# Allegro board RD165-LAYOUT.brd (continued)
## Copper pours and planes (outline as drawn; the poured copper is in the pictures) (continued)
L_GND on BOTTOM: 69,16.69 68.99,16.65 68.97,16.62 68.38,16.03 68.35,16.01 68.31,16 58.17,16 58.01,16.03 57.88,16.12 57.62,16.38 57.53,16.51 57.5,16.67 57.5,52.13 57.53,52.29 57.62,52.42 57.88,52.68 58.01,52.77 58.17,52.8 67.21,52.8 67.25,52.79 67.28,52.77 71.72,48.33 71.74,48.3 71.75,48.26 71.75,36.54 71.74,36.5 71.72,36.47 69.09,33.84 69.02,33.74 69,33.63 ; 8 cut-outs
L_GND on CONDUCTIVE2: 69,16.69 68.99,16.65 68.97,16.62 68.38,16.03 68.35,16.01 68.31,16 58.17,16 58.01,16.03 57.88,16.12 57.62,16.38 57.53,16.51 57.5,16.67 57.5,52.13 57.53,52.29 57.62,52.42 57.88,52.68 58.01,52.77 58.17,52.8 67.21,52.8 67.25,52.79 67.28,52.77 71.72,48.33 71.74,48.3 71.75,48.26 71.75,36.54 71.74,36.5 71.72,36.47 69.09,33.84 69.02,33.74 69,33.63 ; 11 cut-outs
L_GND on CONDUCTIVE3: outline of 86 points within 57.5,16 71.75,52.8 ; 8 cut-outs
Net_1 on BOTTOM: 106.21,-1 106.65,-2.06 107.71,-2.5 109,-2.5 109,-6 1,-6 1,-2.5 2.29,-2.5 3.35,-2.06 3.79,-1 ; 4 cut-outs
Net_2 on BOTTOM: 1,112.5 1,116 109,116 109,112.5 107.71,112.5 106.65,112.06 106.21,111 3.79,111 3.35,112.06 2.29,112.5 ; 4 cut-outs
Net_3 on CONDUCTIVE3: 106.21,-1 106.65,-2.06 107.71,-2.5 109,-2.5 109,-6 1,-6 1,-2.5 2.29,-2.5 3.35,-2.06 3.79,-1 ; 2 cut-outs
Net_4 on CONDUCTIVE3: 1,112.5 1,116 109,116 109,112.5 107.71,112.5 106.65,112.06 106.21,111 3.79,111 3.35,112.06 2.29,112.5 ; 2 cut-outs
Net_5 on CONDUCTIVE2: 106.21,-1 106.65,-2.06 107.71,-2.5 109,-2.5 109,-6 1,-6 1,-2.5 2.29,-2.5 3.35,-2.06 3.79,-1 ; 2 cut-outs
Net_6 on CONDUCTIVE2: 1,112.5 1,116 109,116 109,112.5 107.71,112.5 106.65,112.06 106.21,111 3.79,111 3.35,112.06 2.29,112.5 ; 2 cut-outs
Net_7 on TOP: 106.21,-1 106.65,-2.06 107.71,-2.5 109,-2.5 109,-6 1,-6 1,-2.5 2.29,-2.5 3.35,-2.06 3.79,-1 ; 4 cut-outs
Net_8 on TOP: 1,112.5 1,116 109,116 109,112.5 107.71,112.5 106.65,112.06 106.21,111 3.79,111 3.35,112.06 2.29,112.5 ; 4 cut-outs
O_GND on TOP (solid shape): 85.12,80.86 85.2,80.79 85.22,80.69 85.22,77.5 83.78,77.5 83.78,80.89 85.03,80.89
O_GND on TOP: outline of 102 points within 56.8,1 109,109 ; 7 cut-outs
O_GND on BOTTOM: 57.5,15.08 57.53,15.24 57.62,15.37 57.88,15.63 58.01,15.72 58.17,15.75 68.31,15.75 68.44,15.78 68.56,15.85 69.15,16.44 69.22,16.56 69.25,16.69 69.25,33.6 69.26,33.64 69.28,33.68 71.65,36.04 71.9,36.29 71.97,36.41 72,36.54 72,48.26 71.97,48.39 71.9,48.51 67.46,52.95 67.34,53.02 67.21,53.05 58.17,53.05 58.01,53.08 57.88,53.17 57.62,53.43 57.53,53.56 57.5,53.72 57.5,108.33 57.53,108.49 57.62,108.62 57.88,108.88 58.01,108.97 58.17,109 99.86,109 99.9,108.99 99.93,108.97 100.17,108.73 100.19,108.7 100.2,108.66 100.2,106 101.9,101.9 106,100.2 108.66,100.2 108.7,100.19 108.73,100.17 108.97,99.93 108.99,99.9 109,99.86 109,10.14 108.99,10.1 108.97,10.07 108.73,9.83 108.7,9.81 108.66,9.8 106,9.8 101.9,8.1 100.2,4 100.2,1.34 100.19,1.3 100.17,1.27 99.93,1.03 99.9,1.01 99.86,1 58.17,1 58.01,1.03 57.88,1.12 57.62,1.38 57.53,1.51 57.5,1.67 ; 9 cut-outs
O_GND on CONDUCTIVE2: 57.5,15.08 57.53,15.24 57.62,15.37 57.88,15.63 58.01,15.72 58.17,15.75 68.31,15.75 68.44,15.78 68.56,15.85 69.15,16.44 69.22,16.56 69.25,16.69 69.25,33.6 69.26,33.64 69.28,33.68 71.9,36.29 71.97,36.41 72,36.54 72,48.26 71.97,48.39 71.9,48.51 67.46,52.95 67.34,53.02 67.21,53.05 58.17,53.05 58.01,53.08 57.88,53.17 57.62,53.43 57.53,53.56 57.5,53.72 57.5,108.33 57.53,108.49 57.62,108.62 57.88,108.88 58.01,108.97 58.17,109 99.86,109 99.9,108.99 99.93,108.97 100.17,108.73 100.19,108.7 100.2,108.66 100.2,106 101.9,101.9 106,100.2 108.66,100.2 108.7,100.19 108.73,100.17 108.97,99.93 108.99,99.9 109,99.86 109,10.14 108.99,10.1 108.97,10.07 108.73,9.83 108.7,9.81 108.66,9.8 106,9.8 101.9,8.1 100.2,4 100.2,1.34 100.19,1.3 100.17,1.27 99.93,1.03 99.9,1.01 99.86,1 58.17,1 58.01,1.03 57.88,1.12 57.62,1.38 57.53,1.51 57.5,1.67 ; 13 cut-outs
O_GND on CONDUCTIVE3: outline of 186 points within 57.5,1 109,109 ; 10 cut-outs
P-GND on TOP: outline of 168 points within 29.95,2.25 46.9,19
P-GND on TOP: 23.39,78.4 23.35,78.41 23.32,78.43 23.08,78.67 23.06,78.7 23.05,78.74 23.05,78.79 23.01,79.02 22.88,79.25 22.88,79.28 22.88,79.53 22.88,79.57 22.9,79.6 23.07,79.77 23.1,79.79 23.14,79.8 23.95,79.8 24.23,79.87 24.34,79.96 25.1,80.72 25.13,80.74 25.17,80.75 25.46,80.75 25.54,80.72 25.57,80.65 25.57,79.8 25.54,79.73 25.46,79.7 25.18,79.7 24.98,79.62 24.9,79.42 24.9,78.69 24.89,78.65 24.87,78.62 24.68,78.43 24.65,78.41 24.61,78.4
P-GND on TOP: 52.5,60.81 52.54,60.62 52.65,60.45 53.05,60.05 53.16,59.88 53.2,59.69 53.2,56.31 53.16,56.12 53.05,55.95 52.65,55.55 52.54,55.38 52.5,55.19 52.5,1.67 52.47,1.51 51.99,1.03 51.83,1 10.14,1 10.1,1.01 10.07,1.03 9.83,1.27 9.81,1.3 9.8,1.34 9.8,4 8.1,8.1 4,9.8 1.34,9.8 1.3,9.81 1.27,9.83 1.03,10.07 1.01,10.1 1,10.14 1,99.86 1.01,99.9 1.03,99.93 1.27,100.17 1.3,100.19 1.34,100.2 4,100.2 8.1,101.9 9.8,106 9.8,108.66 9.81,108.7 9.83,108.73 10.07,108.97 10.1,108.99 10.14,109 51.83,109 51.99,108.97 52.12,108.88 52.38,108.62 52.47,108.49 52.5,108.33 ; 28 cut-outs
P-GND on BOTTOM: 52.5,1.67 52.47,1.51 52.38,1.38 51.99,1.03 51.83,1 10.14,1 10.1,1.01 10.07,1.03 9.83,1.27 9.81,1.3 9.8,1.34 9.8,4 8.1,8.1 4,9.8 1.34,9.8 1.3,9.81 1.27,9.83 1.03,10.07 1.01,10.1 1,10.14 1,99.86 1.01,99.9 1.03,99.93 1.27,100.17 1.3,100.19 1.34,100.2 4,100.2 8.1,101.9 9.8,106 9.8,108.66 9.81,108.7 9.83,108.73 10.07,108.97 10.1,108.99 10.14,109 51.83,109 51.99,108.97 52.12,108.88 52.38,108.62 52.38,108.62 52.47,108.49 52.5,108.33 ; 22 cut-outs
P-GND on CONDUCTIVE2: 52.5,1.67 52.47,1.51 52.38,1.38 52.12,1.12 51.99,1.03 51.83,1 10.14,1 10.1,1.01 10.07,1.03 9.83,1.27 9.81,1.3 9.8,1.34 9.8,4 8.1,8.1 4,9.8 1.34,9.8 1.3,9.81 1.27,9.83 1.03,10.07 1.01,10.1 1,10.14 1,99.86 1.01,99.9 1.03,99.93 1.27,100.17 1.3,100.19 1.34,100.2 4,100.2 8.1,101.9 9.8,106 9.8,108.66 9.81,108.7 9.83,108.73 10.07,108.97 10.1,108.99 10.14,109 51.83,109 51.99,108.97 52.12,108.88 52.38,108.62 52.47,108.49 52.5,108.33 ; 40 cut-outs
VOUT on TOP: 103.9,83.5 103.83,83.53 103.8,83.6 103.8,83.99 103.77,84.09 103.74,84.13 102.6,85.28 101.67,85.28 101.6,85.3 101.58,85.38 101.58,85.88 101.6,85.95 101.67,85.97 102.98,85.97 103.02,85.97 103.05,85.95 104.48,84.52 104.57,84.39 104.6,84.23 104.6,83.6 104.57,83.53 104.5,83.5
VOUT on TOP: 80.24,21 80.2,21.01 80.17,21.03 78.18,23.02 78.16,23.05 78.15,23.09 78.15,32.51 78.16,32.55 78.18,32.58 79.27,33.67 79.3,33.69 79.34,33.7 81.91,33.7 81.95,33.69 81.98,33.67 82.52,33.13 82.66,33.03 82.84,33 88.87,33 88.94,33.02 89.01,33.06 89.44,33.49 89.48,33.56 89.5,33.63 89.5,37.96 89.51,38 89.53,38.03 89.77,38.27 89.8,38.29 89.84,38.3 90.6,38.3 90.68,38.32 90.74,38.36 91.04,38.66 91.08,38.72 91.1,38.8 91.1,41.5 91.13,41.57 91.2,41.6 95.8,41.6 95.87,41.57 95.9,41.5 95.9,38.8 95.93,38.7 95.96,38.65 96.05,38.6 96.1,38.59 101.37,38.59 101.4,38.58 101.44,38.56 101.47,38.53 101.49,38.5 101.5,38.46 101.5,23.64 101.49,23.6 101.47,23.57 98.93,21.03 98.9,21.01 98.86,21
VOUT on BOTTOM: 80.24,21 80.2,21.01 80.17,21.03 78.18,23.02 78.16,23.05 78.15,23.09 78.15,32.51 78.16,32.55 78.18,32.58 79.27,33.67 79.3,33.69 79.34,33.7 81.91,33.7 81.95,33.69 81.98,33.67 82.52,33.13 82.66,33.03 82.84,33 88.87,33 88.94,33.02 89.01,33.06 89.44,33.49 89.48,33.56 89.5,33.63 89.5,38.66 89.51,38.7 89.53,38.73 89.77,38.97 89.8,38.99 89.84,39 92.21,39 92.25,38.99 92.28,38.97 92.55,38.7 92.7,38.61 92.8,38.6 100.06,38.6 100.1,38.59 100.13,38.57 101.47,37.23 101.49,37.2 101.5,37.16 101.5,23.64 101.49,23.6 101.47,23.57 98.93,21.03 98.9,21.01 98.86,21
VOUT on CONDUCTIVE2, CONDUCTIVE3: 91.04,31.85 91,31.86 90.97,31.88 90.88,31.97 90.86,32 90.85,32.04 90.85,37.36 90.86,37.4 90.88,37.43 90.97,37.52 91,37.54 91.04,37.55 98.91,37.55 98.95,37.54 98.98,37.52 99.07,37.43 99.09,37.4 99.1,37.36 99.1,33.74 99.09,33.7 99.07,33.67 97.28,31.88 97.25,31.86 97.21,31.85
VOUT on CONDUCTIVE2, CONDUCTIVE3: 87.34,23.05 87.3,23.06 87.27,23.08 87.18,23.17 87.16,23.2 87.15,23.24 87.15,25.16 87.16,25.2 87.18,25.23 87.27,25.32 87.3,25.34 87.34,25.35 92.66,25.35 92.7,25.34 92.73,25.32 92.82,25.23 92.84,25.2 92.85,25.16 92.85,23.24 92.84,23.2 92.82,23.17 92.73,23.08 92.7,23.06 92.66,23.05
VOUT on CONDUCTIVE2, CONDUCTIVE3: 80.94,22 80.9,22.01 80.87,22.03 80.78,22.12 80.76,22.15 80.75,22.19 80.75,24.11 80.76,24.15 80.78,24.18 80.87,24.27 80.9,24.29 80.94,24.3 84.56,24.3 84.6,24.29 84.63,24.27 84.72,24.18 84.74,24.15 84.75,24.11 84.75,22.19 84.74,22.15 84.72,22.12 84.63,22.03 84.6,22.01 84.56,22
VOUT on CONDUCTIVE3: 78.34,24.85 78.3,24.86 78.27,24.88 78.18,24.97 78.16,25 78.15,25.04 78.15,31.61 78.16,31.65 78.18,31.68 79.27,32.77 79.3,32.79 79.34,32.8 80.91,32.8 80.95,32.79 80.98,32.77 84.67,29.08 84.69,29.05 84.7,29.01 84.7,25.24 84.69,25.2 84.67,25.17 84.58,25.08 84.55,25.06 84.51,25.05 80.64,25.05 80.51,25.02 80.4,24.95 80.3,24.86 80.26,24.85
VSEC on TOP: 91.2,47.7 91.13,47.73 91.1,47.8 91.1,50.5 90.9,50.7 77.44,50.7 77.4,50.71 77.37,50.73 76.13,51.97 76.11,52 76.1,52.04 76.1,59.85 76.11,59.89 76.13,59.93 78.87,62.67 78.91,62.69 78.94,62.7 98.91,62.7 98.95,62.69 98.98,62.67 99.12,62.53 99.14,62.5 99.15,62.46 99.15,51.04 99.14,51 99.12,50.97 98.88,50.73 98.85,50.71 98.81,50.7 96.1,50.7 95.9,50.5 95.9,47.8 95.87,47.73 95.8,47.7
VSEC on CONDUCTIVE2, CONDUCTIVE3: 77.29,50.9 77.25,50.91 77.22,50.93 76.28,51.87 76.26,51.9 76.25,51.94 76.25,59.81 76.26,59.85 76.28,59.88 78.07,61.67 78.1,61.69 78.14,61.7 80.06,61.7 80.1,61.69 80.13,61.67 80.22,61.58 80.24,61.55 80.25,61.51 80.25,56.24 80.28,56.11 80.35,56 80.5,55.85 80.61,55.78 80.75,55.75 81.76,55.75 81.8,55.74 81.83,55.72 81.92,55.63 81.94,55.6 81.95,55.56 81.95,53.64 81.94,53.6 81.92,53.57 79.28,50.93 79.25,50.91 79.21,50.9
N04422 on TOP: 4.55,40.1 4.48,40.13 4.45,40.2 4.45,45.01 4.42,45.14 4.35,45.25 2.78,46.82 2.76,46.85 2.75,46.89 2.75,92.81 2.76,92.85 2.78,92.88 16.62,106.72 16.65,106.74 16.69,106.75 35.16,106.75 35.19,106.74 35.23,106.72 35.72,106.23 35.74,106.19 35.75,106.16 35.75,103.45 35.81,103.31 35.95,103.25 43.46,103.25 43.5,103.24 43.53,103.22 43.72,103.03 43.74,103 43.75,102.96 43.75,94.89 43.74,94.85 43.72,94.82 42.68,93.78 42.65,93.76 42.61,93.75 22.15,93.75 22.13,93.74 22.03,93.71 21.94,93.65 16.85,88.56 16.78,88.44 16.75,88.31 16.75,51.4 16.8,51.22 16.85,51.15 17.42,50.58 17.44,50.55 17.45,50.51 17.45,46.19 17.44,46.15 17.42,46.12 16.98,45.68 16.95,45.66 16.91,45.65 15.85,45.65 15.74,45.61 15.7,45.5 15.7,42.85 15.67,42.78 15.6,42.75 7.9,42.75 7.83,42.78 7.8,42.85 7.8,45.5 7.76,45.61 7.65,45.65 6.33,45.65 6.26,45.63 6.19,45.59 5.81,45.21 5.77,45.14 5.75,45.07 5.75,40.2 5.72,40.13 5.65,40.1
N04422 on BOTTOM: 37.04,89.85 37,89.86 36.97,89.88 36.7,90.15 36.68,90.18 36.67,90.22 36.67,92.03 36.65,92.17 36.57,92.28 35.71,93.15 35.59,93.22 35.46,93.25 33.99,93.25 33.96,93.26 33.92,93.28 33.56,93.65 33.52,93.68 32.78,94.42 32.76,94.45 32.75,94.49 32.75,106.46 32.76,106.5 32.78,106.53 32.97,106.72 33,106.74 33.04,106.75 35.16,106.75 35.2,106.74 35.23,106.72 36.2,105.75 36.31,105.68 36.45,105.65 41.74,105.65 41.78,105.64 41.81,105.62 46.72,100.71 46.74,100.68 46.75,100.64 46.75,93.54 46.74,93.5 46.72,93.47 46.45,93.2 46.45,91.59 46.44,91.55 46.42,91.52 46.05,91.15 46.03,91.13 45.72,91.02 45.47,90.85 45.42,90.8 45.21,90.49 45.1,90.11 45.08,90.08 44.88,89.88 44.85,89.86 44.81,89.85
N04422 on CONDUCTIVE2, CONDUCTIVE3: 36.19,94.3 36.15,94.31 36.12,94.33 35.49,94.96 35.35,95.04 35.28,95.05 33.59,95.05 33.55,95.06 33.52,95.08 33.43,95.17 33.41,95.2 33.4,95.24 33.4,106.51 33.41,106.55 33.43,106.58 33.52,106.67 33.55,106.69 33.59,106.7 34.66,106.7 34.7,106.69 34.73,106.67 35.67,105.73 35.69,105.7 35.7,105.66 35.7,99.17 35.74,99.02 35.79,98.96 36.36,98.39 36.5,98.31 36.57,98.3 41.51,98.3 41.55,98.29 41.58,98.27 41.67,98.18 41.69,98.15 41.7,98.11 41.7,94.49 41.69,94.45 41.67,94.42 41.58,94.33 41.55,94.31 41.51,94.3
N04422 on CONDUCTIVE3: 16.25,46.17 16.04,46.26 15.95,46.48 15.95,47.33 16.04,47.54 16.25,47.62 17.1,47.62 17.22,47.6 17.31,47.54 17.71,47.14 17.78,47.04 17.8,46.93 17.8,46.87 17.78,46.76 17.71,46.66 17.31,46.26 17.22,46.2 17.1,46.17
N07195 on TOP: 33.65,76.72 33.58,76.75 33.55,76.83 33.55,79.59 33.52,79.69 33.49,79.73 33.36,79.87 33.27,79.92 33.22,79.92 30.49,79.92 30.45,79.93 30.42,79.95 30.28,80.1 30.26,80.13 30.25,80.17 30.25,80.88 30.26,80.92 30.28,80.95 30.42,81.1 30.45,81.12 30.49,81.12 38.63,81.12 38.67,81.12 38.7,81.1 39.02,80.78 39.04,80.75 39.05,80.71 39.05,80.24 39.04,80.2 39.02,80.17 38.8,79.95 38.77,79.93 38.73,79.92 35.27,79.92 35.13,79.9 35.02,79.82 34.85,79.66 34.78,79.54 34.75,79.41 34.75,77.07 34.74,77.03 34.72,77 34.48,76.75 34.45,76.73 34.41,76.72
N07459 on TOP: 28.69,77.78 28.65,77.78 28.62,77.8 28.38,78.05 28.36,78.08 28.35,78.12 28.35,83.03 28.38,83.1 28.45,83.12 28.93,83.12 28.97,83.12 29,83.1 29.52,82.58 29.54,82.55 29.55,82.51 29.55,77.88 29.52,77.8 29.45,77.78
N07528 on TOP: 37.17,85.78 37.13,85.78 37.1,85.8 31.86,91.04 31.79,91.08 31.72,91.1 24.88,91.1 24.81,91.08 24.74,91.04 24.16,90.46 24.12,90.39 24.1,90.32 24.1,88.78 24.12,88.71 24.16,88.64 24.22,88.58 24.28,88.54 24.36,88.53 24.55,88.53 24.55,90.2 24.55,90.24 24.57,90.27 24.92,90.62 24.95,90.64 24.99,90.65 25.65,90.65 25.72,90.62 25.75,90.55 25.75,89.84 25.74,89.8 25.72,89.77 25.2,89.25 25.15,89.16 25.14,89.11 25.14,87.08 25.12,87 25.05,86.97 23.27,86.97 23.23,86.98 23.2,87 22.33,87.87 22.31,87.9 22.3,87.94 22.3,91.16 22.31,91.2 22.33,91.23 23.97,92.87 24,92.89 24.04,92.9 32.61,92.9 32.65,92.89 32.68,92.87 37.87,87.68 37.99,87.6 38.12,87.58 38.93,87.58 39.07,87.6 39.18,87.68 40.26,88.72 40.29,88.72 40.96,88.72 41,88.72 41.03,88.7 41.37,88.35 41.39,88.32 41.4,88.28 41.4,87.37 41.39,87.33 41.37,87.3 39.88,85.8 39.85,85.78 39.81,85.78
N08453 on TOP: 6.54,21.45 6.5,21.46 6.47,21.48 3.8,24.15 3.78,24.18 3.77,24.22 3.77,33.03 3.78,33.07 3.8,33.1 4.35,33.65 4.42,33.76 4.45,33.9 4.45,38.8 4.48,38.87 4.55,38.9 5.65,38.9 5.72,38.87 5.75,38.8 5.75,33.93 5.77,33.86 5.81,33.79 6.19,33.41 6.26,33.37 6.33,33.35 7.65,33.35 7.76,33.39 7.8,33.5 7.8,34.5 7.83,34.57 7.9,34.6 15.6,34.6 15.67,34.57 15.7,34.5 15.7,33.5 15.74,33.39 15.85,33.35 17.17,33.35 17.27,33.38 17.31,33.41 17.39,33.49 17.44,33.58 17.45,33.63 17.45,36.21 17.46,36.25 17.48,36.28 17.67,36.47 17.7,36.49 17.74,36.5 28.16,36.5 28.2,36.49 28.23,36.47 30.22,34.48 30.24,34.45 30.25,34.41 30.25,28.39 30.24,28.35 30.22,28.32 23.38,21.48 23.35,21.46 23.31,21.45
N08453 on BOTTOM: 23.69,28.15 23.65,28.16 23.62,28.18 23.43,28.37 23.41,28.4 23.4,28.44 23.4,36.21 23.41,36.25 23.43,36.28 23.62,36.47 23.65,36.49 23.69,36.5 27.26,36.5 27.3,36.49 27.33,36.47 30.22,33.58 30.24,33.55 30.25,33.51 30.25,31.62 30.15,31.14 29.88,30.73 27.33,28.18 27.3,28.16 27.26,28.15
N08453 on CONDUCTIVE2, CONDUCTIVE3: 23.69,28.15 23.65,28.16 23.62,28.18 23.43,28.37 23.41,28.4 23.4,28.44 23.4,36.21 23.41,36.25 23.43,36.28 23.62,36.47 23.65,36.49 23.69,36.5 27.26,36.5 27.3,36.49 27.33,36.47 30.22,33.58 30.24,33.55 30.25,33.51 30.25,31.14 30.24,31.1 30.22,31.07 27.33,28.18 27.3,28.16 27.26,28.15
N20934 on TOP: 63.69,65 63.65,65.01 63.62,65.03 62.78,65.87 62.76,65.9 62.75,65.94 62.75,72.38 62.76,72.42 62.78,72.45 64.55,74.23 64.79,74.58 64.88,75.01 64.88,77.93 64.88,77.97 64.9,78 67.6,80.7 67.63,80.72 67.67,80.72 75,80.72 75.43,80.81 75.8,81.05 76.5,81.76 76.54,81.8 76.58,81.85 76.86,82.13 76.89,82.15 76.93,82.16 82.97,82.16 83.05,82.13 83.08,82.06 83.08,79.3 83.05,79.23 82.97,79.2 82.5,79.2 82.5,73.04 82.49,73 82.47,72.97 74.53,65.03 74.5,65.01 74.46,65
N75033 on BOTTOM: 30.19,91.75 30.15,91.76 30.12,91.78 29.88,92.02 29.86,92.05 29.85,92.09 29.85,92.61 29.86,92.65 29.88,92.68 30.12,92.92 30.15,92.94 30.19,92.95 31.61,92.95 31.65,92.94 31.68,92.92 31.82,92.78 31.84,92.75 31.85,92.71 31.85,91.89 31.84,91.85 31.82,91.82 31.78,91.78 31.75,91.76 31.71,91.75
N143611 on TOP: 32.9,5.2 32.83,5.23 32.8,5.3 32.8,8.5 32.83,8.57 32.9,8.6 33.77,8.6 33.87,8.63 33.91,8.66 34.07,8.82 34.12,8.91 34.12,8.96 34.12,9.1 34.15,9.17 34.23,9.2 34.42,9.2 34.5,9.17 34.52,9.1 34.52,7.23 34.52,7.19 34.5,7.16 33.56,6.22 33.51,6.13 33.5,6.08 33.5,5.3 33.47,5.23 33.4,5.2
N147050 on TOP: 38.12,13.5 38.05,13.53 38.02,13.6 38.02,17.33 38.03,17.37 38.05,17.4 39.19,18.54 39.23,18.61 39.25,18.68 39.25,20.1 39.28,20.17 39.35,20.2 39.91,20.2 39.95,20.19 39.98,20.17 40.36,19.79 40.38,19.76 40.39,19.72 40.39,18.44 40.41,18.37 40.45,18.3 40.51,18.26 40.58,18.25 43.3,18.25 43.37,18.22 43.4,18.15 43.4,14.75 43.37,14.68 43.3,14.65 39.53,14.65 39.46,14.63 39.39,14.59 39.13,14.33 39.09,14.27 39.08,14.19 39.08,13.6 39.05,13.53 38.98,13.5
N147857 on TOP: 34.88,13.5 34.8,13.53 34.77,13.6 34.77,15.15 34.78,15.18 34.79,15.21 34.86,15.63 34.61,15.97 34.53,16.05 34.51,16.08 34.5,16.12 34.5,16.75 34.53,16.82 34.6,16.85 35.1,16.85 35.17,16.82 35.2,16.75 35.2,15.17 35.19,15.13 35.17,15.1 35.17,13.6 35.15,13.53 35.08,13.5
N162279 on TOP: 95.99,86.25 95.95,86.26 95.92,86.28 95.28,86.92 95.26,86.95 95.25,86.99 95.25,87.68 95.26,87.72 95.28,87.75 95.36,87.83 95.4,87.9 95.42,87.97 95.42,89.47 95.44,89.55 95.52,89.58 95.92,89.58 95.99,89.55 96.02,89.47 96.02,87.82 96.03,87.74 96.07,87.68 96.34,87.41 96.41,87.37 96.48,87.35 98.72,87.35 98.79,87.37 98.86,87.41 99.62,88.17 99.65,88.19 99.69,88.2 102.58,88.2 102.88,87.9 102.88,87.28 102.85,87.2 102.78,87.17 101.17,87.17 101.13,87.17 101.1,87.15 100.23,86.28 100.2,86.26 100.16,86.25
N181356 on TOP: 32.6,62.8 32.53,62.83 32.5,62.9 32.5,66.3 32.53,66.37 32.6,66.4 34.7,66.4 34.91,66.49 35,66.7 35,71.66 35.01,71.7 35.03,71.73 39.27,75.97 39.3,75.99 39.34,76 46.66,76 46.7,75.99 46.73,75.97 47.22,75.48 47.24,75.45 47.25,75.41 47.25,71.44 47.24,71.4 47.22,71.37 46.98,71.13 46.95,71.11 46.91,71.1 46.25,71.11 45.54,70.85 45.17,70.19 45.16,70.15 45.42,69.27 46.26,68.9 46.71,68.9 46.75,68.89 46.78,68.87 47.07,68.58 47.09,68.55 47.1,68.51 47.1,62.9 47.07,62.83 47,62.8
N193836 on TOP: 69.29,45.35 69.25,45.36 69.22,45.38 68.75,45.85 66.54,45.85 66.5,45.86 66.47,45.88 66.4,45.95 63.55,45.95 63.48,45.98 63.45,46.05 63.45,46.85 63.48,46.92 63.55,46.95 69.03,46.95 69.07,46.94 69.1,46.92 69.88,46.15 70.55,46.15 70.62,46.12 70.65,46.05 70.65,45.45 70.62,45.38 70.55,45.35
N216837 on BOTTOM (solid shape): 30.14,25.3 30.26,25.26 30.3,25.14 30.25,23.95 30.1,23.8 29.95,23.95 29.96,24.19 29.19,24.96 28.96,24.95 28.8,25.09 28.95,25.25

Small or netless copper shapes (teardrops, artwork), in the pictures only: 27 on TOP, 11 on BOTTOM, 3 on CONDUCTIVE3, 2 on CONDUCTIVE2

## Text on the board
Ref Des/Silkscreen Bottom: R35 | C36 | R5 | CN1 | CN2 | R7 | R6 | CN3 | G | D | S | C4 | C3 | 1 | Q1 | Q2 | C5 | C61 | C62 | C64 | C63 | CN5 | CN4 | C73 | C74 | PAD5 | PAD6 | PAD2 | PAD3 | PAD7 | PAD4 | D1 | R36 | GND IN | ENABLE | DC IN | 12V OUT | GND OUT
Ref Des/Silkscreen Top: IC3 | R34 | 8 | 1 | R39 | C35 | IC1 | C31 | 4 | 5 | TP1 | C6 | TP9 | R46 | C25 | R25 | Q3 | 3 | R8 | R23 | R2 | C23 | R9 | R24 | R10 | 9 | D3 | R37 | C39 | C38 | PAD3 | PAD6 | C8 | R3 | C24 | PAD2 | PAD5 | R22 | R21 | IC2 | PAD7 | PAD4 | C22 | C26 | C1 | L3 | TP8 | C33 | C51 | T1 | TP19 | R64 | C43 | R74 | C41 | IC8 | IC9 | R71 | O-GND | L-GND | R66 | R72 | C56 | PAD15 | PAD12 | PAD16 | PAD13 | PAD14 | PAD17 | C71 | TP11 | R51 | IC7 | C52 | 16 | R1 | 2 | L1 | J1 | R33 | R31 | R38 | C32 | Q8 | R32 | D2 | C7 | C11 | C21 | R4 | C34 | R43 | C2 | R45 | R44 | IC4 | R41 | R42 | IC5 | IC6 | Q7 | C45 | R63 | R62 | D5 | R75 | R61 | C42 | R67 | 10 | 6 | R73 | D6 | C46 | R65 | C54 | D4 | R48 | Q6 | Q5 | C69 | L2 | C65 | C66 | C72 | C67 | R52 | C68 | C53 | R53 | (ON:SHORT) | REMOTE | P-GND | CURRENT | SENSE | GND IN | ENABLE | DC IN | D | G | S | 12.3V | 10V | GND OUT | 12V OUT
